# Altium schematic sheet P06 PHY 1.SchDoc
size 420 x 297 mm
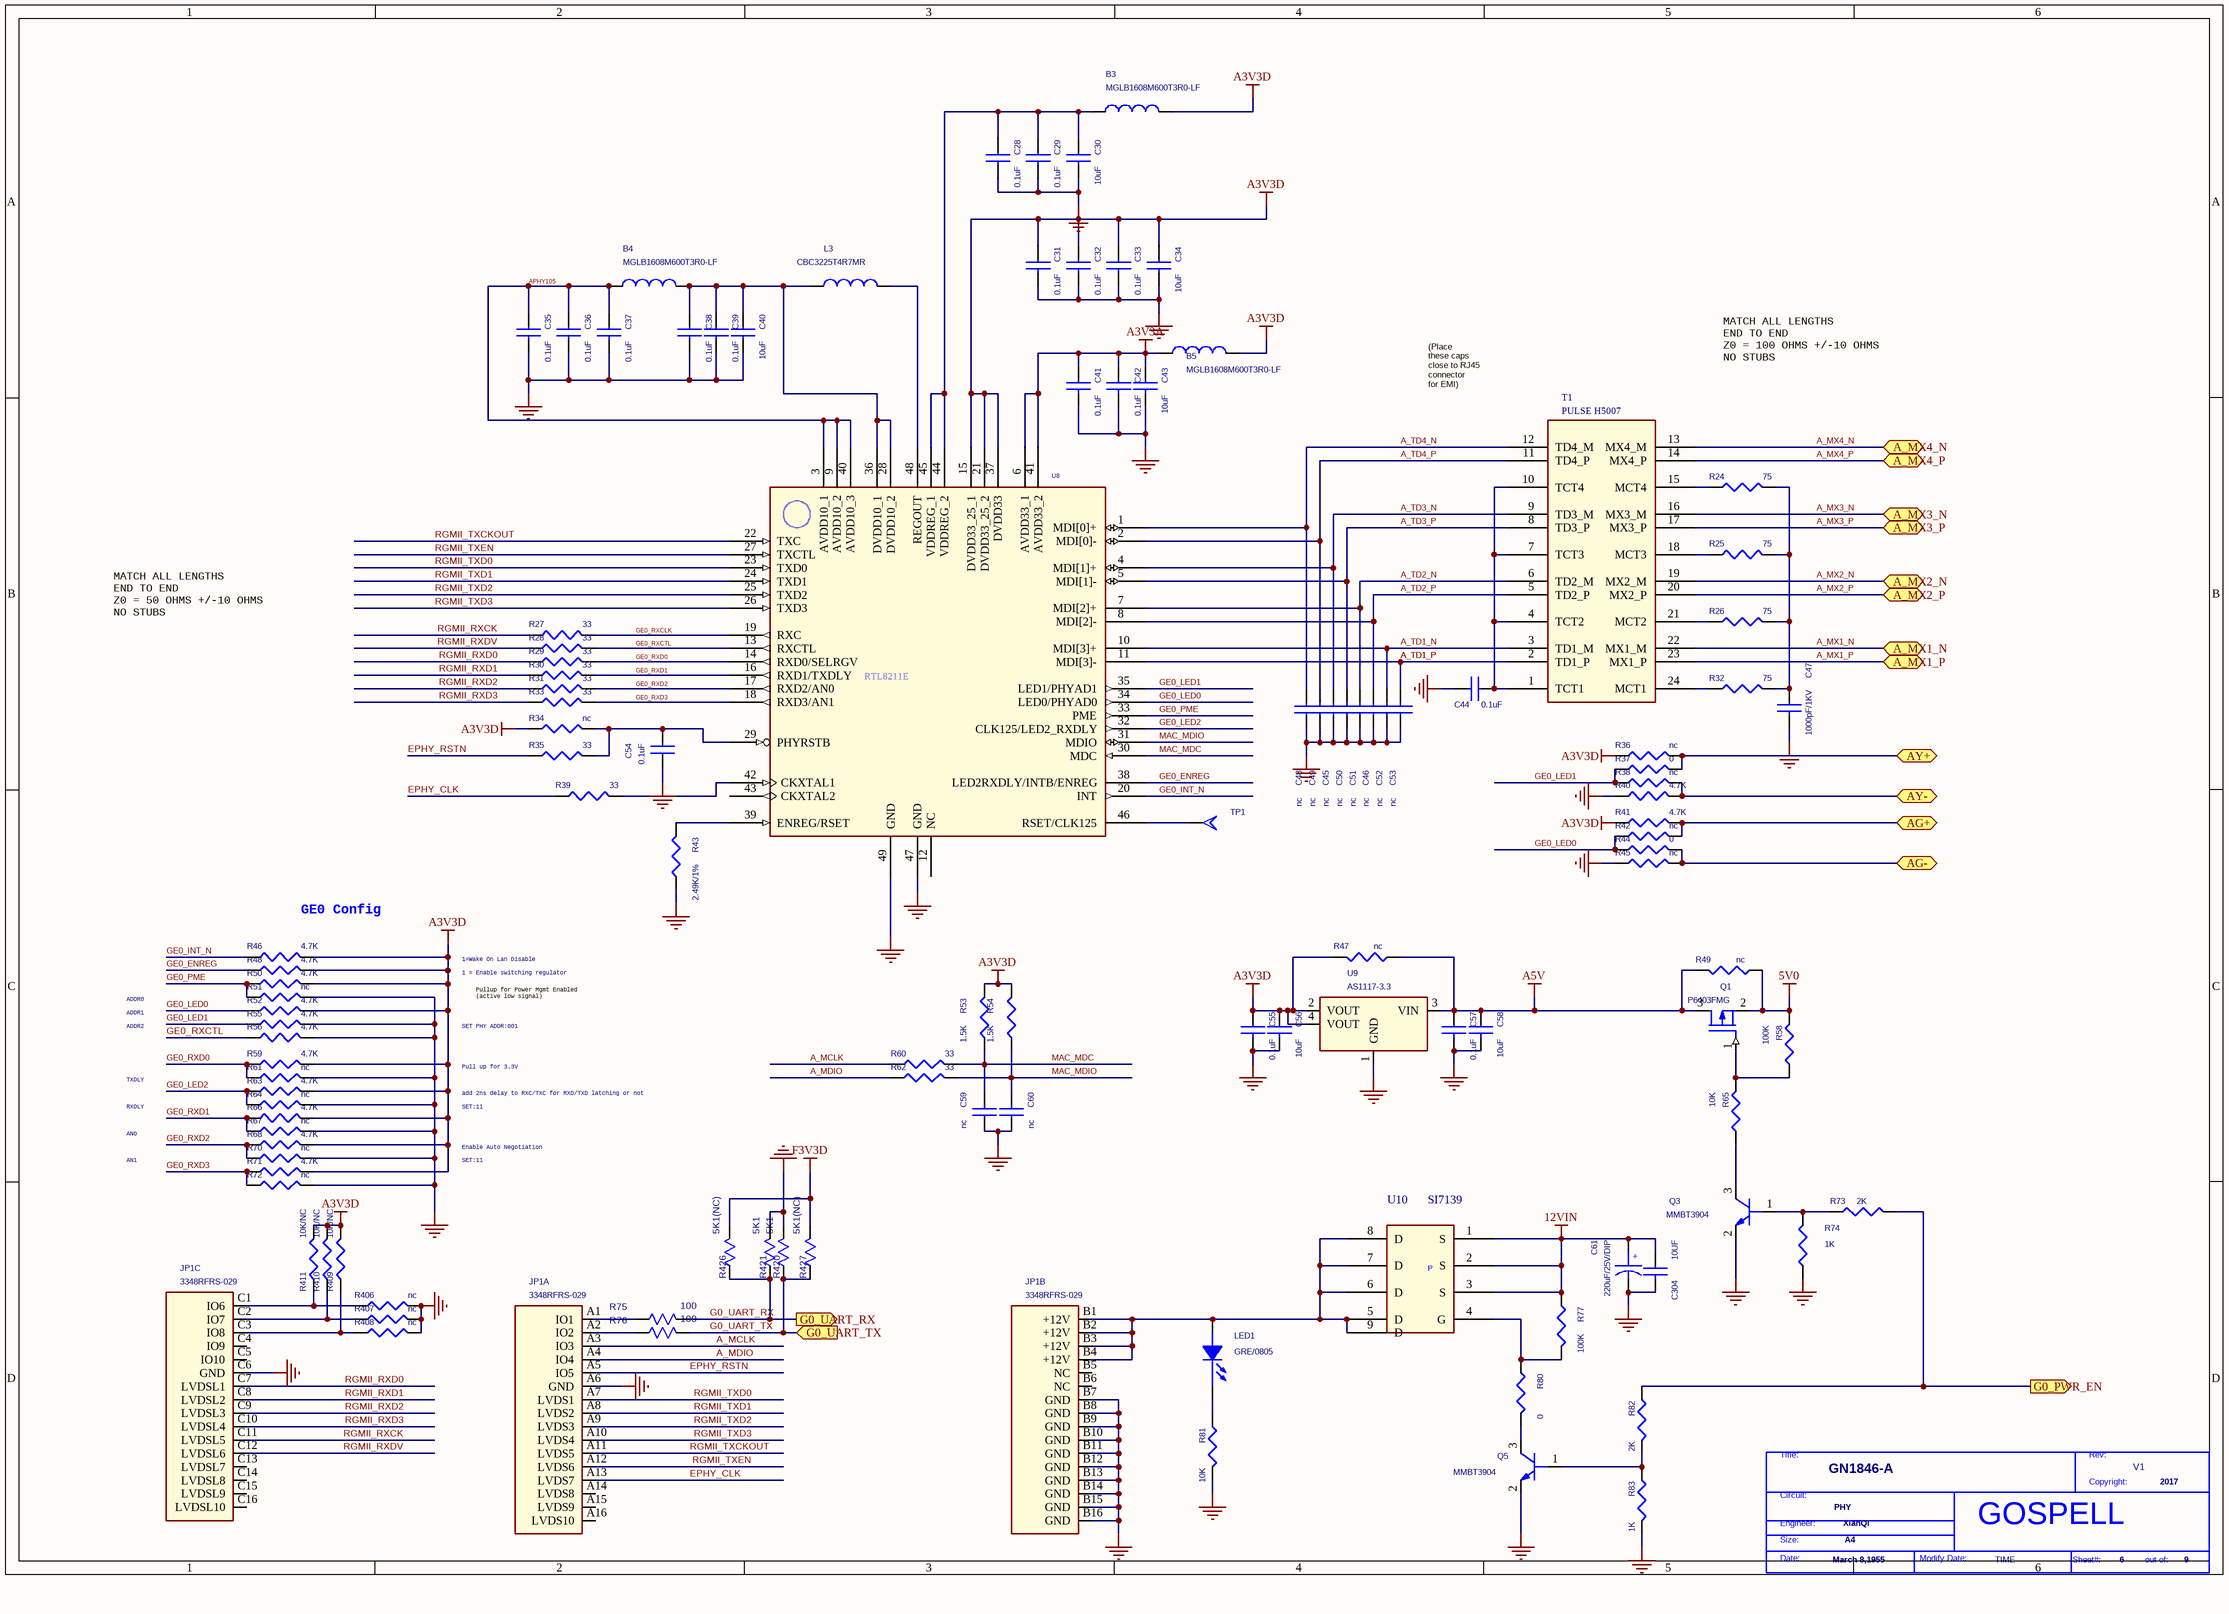
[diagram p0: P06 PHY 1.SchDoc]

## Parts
*  Doc: PHY  Page Count: 9  Page Number: 6  Page Create Date: March 8,1955  Page Size: A4  RevCode: V1  Title: GN1846-A  Copyright: 2017  Engineer: XianQi  Page Modify Date: TIME  (hidden comment: GOSPELL)  (graphical)
B3  MGLB1608M600T3R0-LF  [L0603]
B4  MGLB1608M600T3R0-LF  [L0603]
B5  MGLB1608M600T3R0-LF  [L0603]
C28  0.1uF  [0402C]
C29  0.1uF  [0402C]
C30  10uF  [C0603]
C31  0.1uF  [0402C]
C32  0.1uF  [0402C]
C33  0.1uF  [0402C]
C34  10uF  [C0603]
C35  0.1uF  [0402C]
C36  0.1uF  [0402C]
C37  0.1uF  [0402C]
C38  0.1uF  [0402C]
C39  0.1uF  [0402C]
C40  10uF  [C0603]
C41  0.1uF  [0402C]
C42  0.1uF  [0402C]
C43  10uF  [C0603]
C44  0.1uF  [0402C]
C45  nc  [0402C]
C46  nc  [0402C]
C47  1000pF/1KV  [C1206]
C48  nc  [0402C]
C49  nc  [0402C]
C50  nc  [0402C]
C51  nc  [0402C]
C52  nc  [0402C]
C53  nc  [0402C]
C54  0.1uF  [0402C]
C55  0.1uF  [0402C]
C56  10uF  [C0603]
C57  0.1uF  [0402C]
C58  10uF  [C0603]
C59  nc  [0402C]
C60  nc  [0402C]
C61  220uF/25V/DIP  [CE8X3.5]
C304  10UF  [C1206]
JP1  3348RFRS-029  [3348RFRS-029]  (parts A,B,C of 3)
L3  CBC3225T4R7MR  [FB0805]
LED1  GRE/0805  [LED0805]
Q1  P6403FMG  [SOT23]
Q3  MMBT3904  [SOT23]
Q5  MMBT3904  [SOT23]
R24  75  [0402R]
R25  75  [0402R]
R26  75  [0402R]
R27  33  [0402R]
R28  33  [0402R]
R29  33  [0402R]
R30  33  [0402R]
R31  33  [0402R]
R32  75  [0402R]
R33  33  [0402R]
R34  nc  [0402R]
R35  33  [0402R]
R36  nc  [0402R]
R37  0  [0402R]
R38  nc  [0402R]
R39  33  [0402R]
R40  4.7K  [0402R]
R41  4.7K  [0402R]
R42  nc  [0402R]
R43  2.49K/1%  [0402R]
R44  0  [0402R]
R45  nc  [0402R]
R46  4.7K  [0402R]
R47  nc  [R0603]
R48  4.7K  [0402R]
R49  nc  [R0603]
R50  4.7K  [0402R]
R51  nc  [0402R]
R52  4.7K  [0402R]
R53  1.5K  [0402R]
R54  1.5K  [0402R]
R55  4.7K  [0402R]
R56  4.7K  [0402R]
R58  100K  [0402R]
R59  4.7K  [0402R]
R60  33  [0402R]
R61  nc  [0402R]
R62  33  [0402R]
R63  4.7K  [0402R]
R64  nc  [0402R]
R65  10K  [0402R]
R66  4.7K  [0402R]
R67  nc  [0402R]
R68  4.7K  [0402R]
R70  nc  [0402R]
R71  4.7K  [0402R]
R72  nc  [0402R]
R73  2K  [0402R]
R74  1K  [0402R]
R75  100  [0402R]
R76  100  [0402R]
R77  100K  [R0603]
R80  0  [0402R]
R81  10K  [0402R]
R82  2K  [0402R]
R83  1K  [0402R]
R406  nc  [0402R]
R407  nc  [0402R]
R408  nc  [0402R]
R409  10K/NC  [0402R]
R410  10K/NC  [0402R]
R411  10K/NC  [0402R]
R420  5K1  [0402R]
R421  5K1  [0402R]
R426  5K1(NC)  [0402R]
R427  5K1(NC)  [0402R]
T1  PULSE H5007  [H5007-H]
TP1  T POINT A  [TP_G]  (value not drawn)
U8  RTL8211D  [QFN-48P-RTL8211]  (value not drawn)
U9  AS1117-3.3  [SOT223]
U10  SI7139  [PowerPAKSO8]

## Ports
A_MX1_N (bidir), A_MX1_P (bidir), A_MX2_N (bidir), A_MX2_P (bidir), A_MX3_N (bidir), A_MX3_P (bidir), A_MX4_N (bidir), A_MX4_P (bidir), AG+ (bidir), AG- (bidir), AY+ (bidir), AY- (bidir), G0_PWR_EN (out), G0_UART_RX (out), G0_UART_TX (in)

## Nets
5V0: Q1.2(SOURCE) R49.2 R58.1
12VIN: C61.1 C304.1 R77.2 U10.1(S) U10.2(S) U10.3(S)
A3V3A: B5.1 C41.1 C42.1 C43.1 U8.6(AVDD33_1) U8.41(AVDD33_2)
A3V3D: B3.2 B5.2 C31.1 C32.1 C33.1 C34.1 C55.1 C56.1 R34.1 R36.1 R41.1 R46.2 R47.1 R48.2 R50.2 R52.2 R53.2 R54.2 R59.2 R63.2 R66.2 R68.2 R71.2 R409.2 R410.2 R411.2 U8.15(DVDD33_25_1) U8.21(DVDD33_25_2) U8.37(DVDD33) U9.2(VOUT) U9.4(VOUT)
A5V: C57.1 C58.1 Q1.3(DRAIN) R47.2 R49.1 U9.3(VIN)
F3V3D: R426.2(B) R427.2(B)
GND: C28.2 C29.2 C30.2 C31.2 C32.2 C33.2 C34.2 C35.2 C36.2 C37.2 C38.2 C39.2 C40.2 C41.2 C42.2 C43.2 C44.2 C45.1 C46.1 C47.2 C48.1 C49.1 C50.1 C51.1 C52.1 C53.1 C54.1 C55.2 C56.2 C57.2 C58.2 C59.1 C60.1 C61.2 C304.2 JP1.A6(GND) JP1.B7(GND) JP1.B8(GND) JP1.B9(GND) JP1.B10(GND) JP1.B11(GND) JP1.B12(GND) JP1.B13(GND) JP1.B14(GND) JP1.B15(GND) JP1.B16(GND) JP1.C6(GND) Q3.2(EMITTER) Q5.2(EMITTER) R40.1 R43.1 R45.1 R51.2 R55.2 R56.2 R61.2 R64.2 R67.2 R70.2 R72.2 R74.1 R81.1 R83.1 R406.2 R407.2 R408.2 R420.2(B) R421.2(B) U8.47(GND) U8.49(GND) U9.1(GND)
A_MCLK: JP1.A3(IO3) R60.1
A_MDIO: JP1.A4(IO4) R62.1
A_MX1_N: T1.22(MX1_M) ; port A_MX1_N
A_MX1_P: T1.23(MX1_P) ; port A_MX1_P
A_MX2_N: T1.19(MX2_M) ; port A_MX2_N
A_MX2_P: T1.20(MX2_P) ; port A_MX2_P
A_MX3_N: T1.16(MX3_M) ; port A_MX3_N
A_MX3_P: T1.17(MX3_P) ; port A_MX3_P
A_MX4_N: T1.13(MX4_M) ; port A_MX4_N
A_MX4_P: T1.14(MX4_P) ; port A_MX4_P
A_TD1_N: C52.2 T1.3(TD1_M) U8.10(MDI[3]+)
A_TD1_P: C53.2 T1.2(TD1_P) U8.11(MDI[3]-)
A_TD2_N: C51.2 T1.6(TD2_M) U8.7(MDI[2]+)
A_TD2_P: C46.2 T1.5(TD2_P) U8.8(MDI[2]-)
A_TD3_N: C45.2 T1.9(TD3_M) U8.4(MDI[1]+)
A_TD3_P: C50.2 T1.8(TD3_P) U8.5(MDI[1]-)
A_TD4_N: C48.2 T1.12(TD4_M) U8.1(MDI[0]+)
A_TD4_P: C49.2 T1.11(TD4_P) U8.2(MDI[0]-)
AG+: R41.2 R42.2 ; port AG+
AG-: R44.2 R45.2 ; port AG-
APHY105: B4.1 C35.1 C36.1 C37.1 U8.3(AVDD10_1) U8.9(AVDD10_2) U8.40(AVDD10_3)
AY+: R36.2 R37.2 ; port AY+
AY-: R38.2 R40.2 ; port AY-
EPHY_CLK: JP1.A13(LVDS7) R39.1
EPHY_RSTN: JP1.A5(IO5) R35.1
G0_PWR_EN: R73.2 R82.2 ; port G0_PWR_EN
G0_UART_RX: R75.2(B) R421.1(A) R426.1(A) ; port G0_UART_RX
G0_UART_TX: R76.2(B) R420.1(A) R427.1(A) ; port G0_UART_TX
GE0_ENREG: R48.1 U8.38(LED2RXDLY/INTB/ENREG)
GE0_INT_N: R46.1 U8.20(INT)
GE0_LED0: R42.1 R44.1 R52.1 U8.34(LED0/PHYAD0)
GE0_LED1: R37.1 R38.1 R55.1 U8.35(LED1/PHYAD1)
GE0_LED2: R63.1 R64.1 U8.32(CLK125/LED2_RXDLY)
GE0_PME: R50.1 R51.1 U8.33(PME)
GE0_RXCLK: R27.2 U8.19(RXC)
GE0_RXCTL: R28.2 R56.1 U8.13(RXCTL)
GE0_RXD0: R29.2 R59.1 R61.1 U8.14(RXD0/SELRGV)
GE0_RXD1: R30.2 R66.1 R67.1 U8.16(RXD1/TXDLY)
GE0_RXD2: R31.2 R68.1 R70.1 U8.17(RXD2/AN0)
GE0_RXD3: R33.2 R71.1 R72.1 U8.18(RXD3/AN1)
MAC_MDC: C59.2 R53.1 R60.2 U8.30(MDC)
MAC_MDIO: C60.2 R54.1 R62.2 U8.31(MDIO)
RGMII_RXCK: JP1.C11(LVDSL5) R27.1
RGMII_RXD0: JP1.C7(LVDSL1) R29.1
RGMII_RXD1: JP1.C8(LVDSL2) R30.1
RGMII_RXD2: JP1.C9(LVDSL3) R31.1
RGMII_RXD3: JP1.C10(LVDSL4) R33.1
RGMII_RXDV: JP1.C12(LVDSL6) R28.1
RGMII_TXCKOUT: JP1.A11(LVDS5) U8.22(TXC)
RGMII_TXD0: JP1.A7(LVDS1) U8.23(TXD0)
RGMII_TXD1: JP1.A8(LVDS2) U8.24(TXD1)
RGMII_TXD2: JP1.A9(LVDS3) U8.25(TXD2)
RGMII_TXD3: JP1.A10(LVDS4) U8.26(TXD3)
RGMII_TXEN: JP1.A12(LVDS6) U8.27(TXCTL)
NetB3_1: B3.1 C28.1 C29.1 C30.1 U8.44(VDDREG_2) U8.45(VDDREG_1)
NetB4_2: B4.2 C38.1 C39.1 C40.1 L3.1 U8.28(DVDD10_2) U8.36(DVDD10_1)
NetC44_1: C44.1 T1.1(TCT1) T1.4(TCT2) T1.7(TCT3) T1.10(TCT4)
NetC47_1: C47.1 R24.2 R25.2 R26.2 R32.2
NetC54_2: C54.2 R34.2 R35.2 U8.29(PHYRSTB)
NetJP1_A1: JP1.A1(IO1) R75.1(A)
NetJP1_A2: JP1.A2(IO2) R76.1(A)
NetJP1_B1: JP1.B1(+12V) JP1.B2(+12V) JP1.B3(+12V) JP1.B4(+12V) LED1.A(ANODE) U10.5(D) U10.6(D) U10.7(D) U10.8(D) U10.9(D)
NetJP1_C1: JP1.C1(IO6) R406.1 R411.1
NetJP1_C2: JP1.C2(IO7) R407.1 R410.1
NetJP1_C3: JP1.C3(IO8) R408.1 R409.1
NetL3_2: L3.2 U8.48(REGOUT)
NetLED1_K: LED1.K(CATHODE) R81.2
NetQ1_1: Q1.1(GATE) R58.2 R65.1
NetQ3_1: Q3.1(BASE) R73.1 R74.2
NetQ3_3: Q3.3(COLLECTOR) R65.2
NetQ5_1: Q5.1(BASE) R82.1 R83.2
NetQ5_3: Q5.3(COLLECTOR) R80.1
NetR24_1: R24.1 T1.15(MCT4)
NetR25_1: R25.1 T1.18(MCT3)
NetR26_1: R26.1 T1.21(MCT2)
NetR32_1: R32.1 T1.24(MCT1)
NetR39_2: R39.2 U8.42(CKXTAL1)
NetR43_2: R43.2 U8.39(ENREG/RSET)
NetR77_1: R77.1 R80.2 U10.4(G)
NetTP1_1: TP1.1(TP) U8.46(RSET/CLK125)

Not connected (* = marked no-connect by the designer): JP1 A14(LVDS8) A15(LVDS9) A16(LVDS10) B5(NC) B6(NC) C4(IO9) C5(IO10) C13(LVDSL7) C14(LVDSL8) C15(LVDSL9) C16(LVDSL10); U8 12(NC) 43(CKXTAL2)

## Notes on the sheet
- (Place
  these caps
  close to RJ45
  connector
  for EMI)
- MATCH ALL LENGTHS
  END TO END
  Z0 = 100 OHMS +/-10 OHMS
  NO STUBS
- MATCH ALL LENGTHS
  END TO END
  Z0 = 50 OHMS +/-10 OHMS
  NO STUBS
- GE0 Config
- 1 = Enable switching regulator
- 1=Wake On Lan Disable
- Pullup for Power Mgmt Enabled
  (active low signal)
- ADDR0
- ADDR1
- ADDR2
- SET PHY ADDR:001
- Pull up for 3.3V
- TXDLY
- RXDLY
- add 2ns delay to RXC/TXC for RXD/TXD latching or not
- SET:11
- AN0
- AN1
- Enable Auto Negotiation

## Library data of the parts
B3-B5 L3 = CHOKE TORROID_0
C28-C60 = CAP NP_Dup1
C61 = CAP POL
C304 = CAP NP
LED1 = LED_1
Q1 = MOSFET P_0
Q3 Q5 = 2N3904
R24-R46 R48 R50-R56 R59-R64 R66-R68 R70-R72 R77 R80-R83 R406-R411 = R_Dup1
R47 R49 R58 R65 R73 R74 = R
R75 R76 = R_1: PARTS: 1; OriginalSymbolOrigin: (10,20); PINSWAP: (A,B); DEVICE: RK73H1JTTD7502F; PKG_TYPE: SR0603; LEVEL: STD; CODE: 7091238; %195%%232%%202%%246%: 片式厚膜电阻器-0.1W-75000OHM-+/-1%-0603; %182%%238%%182%%168%%185%%166%%194%%202%(W): 0.1; %215%%232%%214%%181%%212%%202%%208%%237%%198%%171%%178%%238%: +/-1%; COMPONENT_HIGH_MAX: 0.55MM; %208%%161%%192%%224%%195%%251%%179%%198%: 片式厚膜电阻器
R420 R421 R426 R427 = R_1: PARTS: 1; OriginalSymbolOrigin: (10,20); PINSWAP: (A,B); DEVICE: RK73H1JTTD7502F; PKG_TYPE: SR0603; LEVEL: STD; %208%%161%%192%%224%%195%%251%%179%%198%: 片式厚膜电阻器; COMPONENT_HIGH_MAX: 0.55MM; %215%%232%%214%%181%%212%%202%%208%%237%%198%%171%%178%%238%: +/-1%; %182%%238%%182%%168%%185%%166%%194%%202%(W): 0.1; %195%%232%%202%%246%: 片式厚膜电阻器-0.1W-75000OHM-+/-1%-0603; CODE: 7091238
T1 = PULSE H5007_0
U8 = RTL8211D_2
U9 = AS1117-X_3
